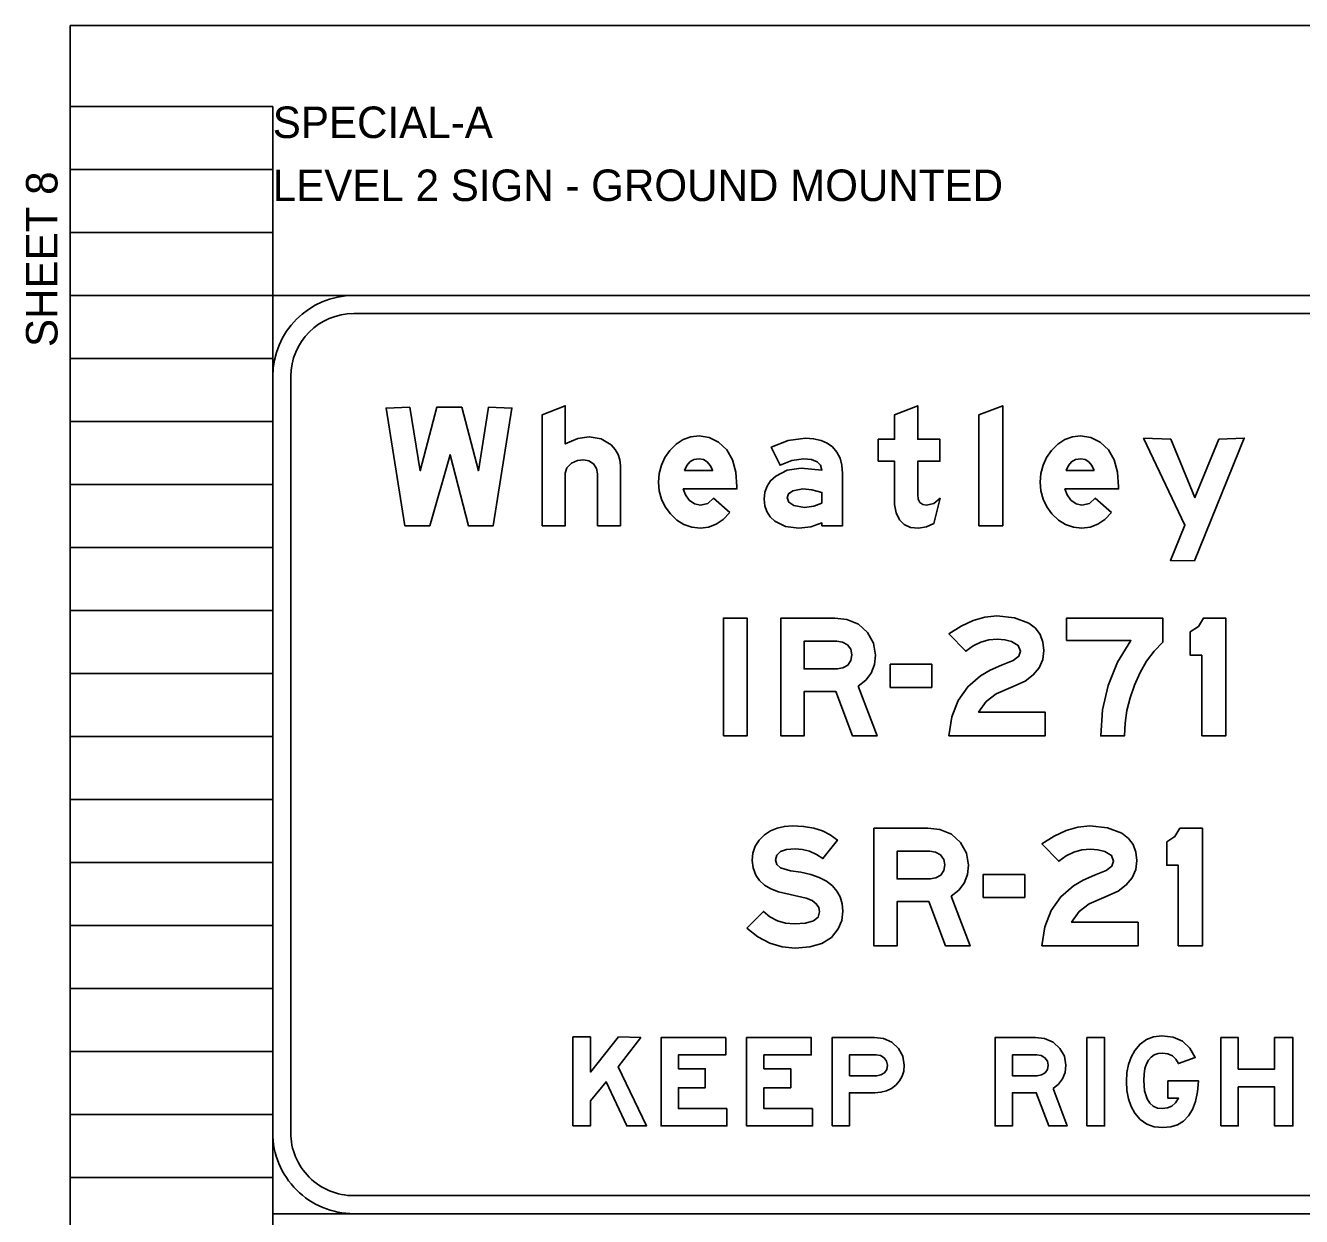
# Model space of a CAD drawing. Extents: x 1820207 to 1820557, y 740216 to 740315.
# Drawn here: x 1820476.25 to 1820481.92, y 740270.45 to 740275.74 of the extents above; entities that cross this region are included whole.
import ezdxf

# ---------------------------------------------------------------- set-up
doc = ezdxf.new("R2010")
doc.units = 0
for name, color, linetype in [('SC_Scratch1', 7, 'Continuous'), ('SC_Scratch2', 7, 'Continuous'), ('SC_Scratch3', 7, 'Continuous'), ('SH_Text', 7, 'Continuous')]:
    doc.layers.add(name, color=color, linetype=linetype)

msp = doc.modelspace()

# ---------------------------------------------------------------- linework, layer by layer
at = {"layer": 'SC_Scratch1'}
for p, q in [((1820476.451, 740255.2219), (1820476.451, 740275.3819)), ((1820476.451, 740275.3819), (1820477.351, 740275.3819)), ((1820477.351, 740255.2219), (1820477.351, 740275.3819)), ((1820476.451, 740275.1019), (1820477.351, 740275.1019)), ((1820476.451, 740274.8219), (1820477.351, 740274.8219)), ((1820476.451, 740274.5419), (1820477.351, 740274.5419)), ((1820476.451, 740274.2619), (1820477.351, 740274.2619)), ((1820476.451, 740273.9819), (1820477.351, 740273.9819)), ((1820476.451, 740273.7019), (1820477.351, 740273.7019)), ((1820476.451, 740273.4219), (1820477.351, 740273.4219)), ((1820476.451, 740273.1419), (1820477.351, 740273.1419)), ((1820476.451, 740272.8619), (1820477.351, 740272.8619)), ((1820476.451, 740272.5819), (1820477.351, 740272.5819)), ((1820476.451, 740272.3019), (1820477.351, 740272.3019)), ((1820476.451, 740272.0219), (1820477.351, 740272.0219)), ((1820476.451, 740271.7419), (1820477.351, 740271.7419)), ((1820476.451, 740271.4619), (1820477.351, 740271.4619)), ((1820476.451, 740271.1819), (1820477.351, 740271.1819)), ((1820476.451, 740270.9019), (1820477.351, 740270.9019)), ((1820476.451, 740270.6219), (1820477.351, 740270.6219))]:
    msp.add_line(p, q, dxfattribs=at)
at = {"layer": 'SC_Scratch2'}
msp.add_lwpolyline([(1820476.451, 740275.7419), (1820506.951, 740275.7419), (1820506.951, 740254.7419), (1820476.451, 740254.7419)], close=True, dxfattribs=at)
at = {"layer": 'SC_Scratch3'}
for points in [[(1820477.351, 740270.4619), (1820483.591, 740270.4619), (1820483.591, 740274.5419), (1820477.351, 740274.5419), (1820477.351, 740270.4619), (1820477.351, 740270.4619), (1820477.351, 740270.4619)], [(1820477.711, 740274.5419), (1820483.231, 740274.5419)], [(1820483.231, 740274.4619), (1820477.711, 740274.4619)], [(1820477.351, 740270.8219), (1820477.351, 740274.1819)], [(1820477.431, 740274.1819), (1820477.431, 740270.8219)], [(1820477.431, 740274.1819), (1820477.431, 740274.1819), (1820477.431, 740274.1819)], [(1820477.711, 740270.5419), (1820483.231, 740270.5419)], [(1820477.711, 740270.5419), (1820477.711, 740270.5419), (1820477.711, 740270.5419)], [(1820483.231, 740270.4619), (1820477.711, 740270.4619)]]:
    msp.add_lwpolyline(points, dxfattribs=at)
for points in [[(1820477.9378, 740273.5186), (1820478.0485, 740273.5186), (1820478.1392, 740273.8346), (1820478.2205, 740273.5186), (1820478.3312, 740273.5186), (1820478.4141, 740274.0416), (1820478.3091, 740274.0459), (1820478.2649, 740273.7632), (1820478.191, 740274.0459), (1820478.0801, 740274.0459), (1820478.0064, 740273.7632), (1820477.9599, 740274.0459), (1820477.855, 740274.0416)], [(1820478.5483, 740273.5186), (1820478.6508, 740273.5186), (1820478.6508, 740273.7532), (1820478.6578, 740273.7766), (1820478.6792, 740273.7964), (1820478.7048, 740273.8083), (1820478.7316, 740273.8123), (1820478.7561, 740273.8076), (1820478.7763, 740273.7938), (1820478.7897, 740273.7735), (1820478.7944, 740273.7495), (1820478.7944, 740273.5186), (1820478.8963, 740273.5186), (1820478.8963, 740273.7849), (1820478.8936, 740273.8112), (1820478.8859, 740273.8355), (1820478.8728, 740273.8576), (1820478.8547, 740273.8778), (1820478.8101, 740273.9051), (1820478.7578, 740273.9142), (1820478.7061, 740273.9062), (1820478.6508, 740273.8825), (1820478.6508, 740274.0519), (1820478.5483, 740274.0115)], [(1820480.0416, 740273.8058), (1820480.1144, 740273.8058), (1820480.1139, 740273.6139), (1820480.1208, 740273.5763), (1820480.1358, 740273.5457), (1820480.1575, 740273.5242), (1820480.1856, 740273.5118), (1820480.2205, 740273.5084), (1820480.2568, 740273.5143), (1820480.2896, 740273.5293), (1820480.3169, 740273.641), (1820480.2892, 740273.6184), (1820480.2568, 740273.6108), (1820480.2394, 740273.6138), (1820480.2271, 740273.6226), (1820480.2196, 740273.6371), (1820480.2172, 740273.6576), (1820480.2172, 740273.8058), (1820480.316, 740273.8058), (1820480.316, 740273.9037), (1820480.2172, 740273.9037), (1820480.2172, 740274.0519), (1820480.1144, 740274.012), (1820480.1144, 740273.9037), (1820480.0416, 740273.9037)], [(1820480.4896, 740273.5186), (1820480.595, 740273.5186), (1820480.595, 740274.0519), (1820480.4896, 740274.0115)], [(1820479.3821, 740273.5778), (1820479.3098, 740273.6415), (1820479.2841, 740273.6184), (1820479.2513, 740273.6108), (1820479.2249, 740273.6163), (1820479.2018, 740273.6332), (1820479.1848, 740273.6558), (1820479.1754, 740273.6826), (1820479.4137, 740273.6826), (1820479.4137, 740273.6915), (1820479.4091, 740273.7575), (1820479.3942, 740273.8126), (1820479.3685, 740273.8569), (1820479.3324, 740273.8905), (1820479.2901, 740273.9115), (1820479.2454, 740273.9186), (1820479.2085, 740273.9144), (1820479.1748, 740273.9022), (1820479.144, 740273.8819), (1820479.1162, 740273.8537), (1820479.094, 740273.8216), (1820479.0783, 740273.7876), (1820479.0686, 740273.7514), (1820479.0656, 740273.7131), (1820479.0688, 740273.6737), (1820479.0786, 740273.6371), (1820479.0949, 740273.603), (1820479.1179, 740273.5716), (1820479.1464, 740273.5437), (1820479.1783, 740273.524), (1820479.2132, 740273.5122), (1820479.2513, 740273.5084), (1820479.288, 740273.5127), (1820479.3221, 740273.5256), (1820479.3534, 740273.5472)], [(1820479.7913, 740273.5186), (1820479.8835, 740273.5186), (1820479.8835, 740273.7514), (1820479.8806, 740273.7875), (1820479.8725, 740273.8192), (1820479.8585, 740273.8463), (1820479.8393, 740273.869), (1820479.8156, 740273.886), (1820479.7875, 740273.8983), (1820479.7548, 740273.9058), (1820479.718, 740273.9083), (1820479.6412, 740273.8983), (1820479.5665, 740273.8687), (1820479.6059, 740273.7881), (1820479.6583, 740273.8089), (1820479.7104, 740273.816), (1820479.7447, 740273.8128), (1820479.7697, 740273.8035), (1820479.7851, 740273.7878), (1820479.7913, 740273.766), (1820479.6993, 740273.775), (1820479.6373, 740273.7662), (1820479.5861, 740273.7397), (1820479.5636, 740273.7188), (1820479.5476, 740273.6948), (1820479.538, 740273.6676), (1820479.535, 740273.6371), (1820479.5378, 740273.6076), (1820479.5466, 740273.5817), (1820479.5612, 740273.5591), (1820479.5817, 740273.5399), (1820479.6298, 740273.5162), (1820479.6893, 740273.5084), (1820479.7421, 740273.5142), (1820479.7913, 740273.5317)], [(1820481.0781, 740273.5778), (1820481.0058, 740273.6415), (1820480.9801, 740273.6184), (1820480.9473, 740273.6108), (1820480.9209, 740273.6163), (1820480.8978, 740273.6332), (1820480.8808, 740273.6558), (1820480.8714, 740273.6826), (1820481.1097, 740273.6826), (1820481.1097, 740273.6915), (1820481.1051, 740273.7575), (1820481.0902, 740273.8126), (1820481.0645, 740273.8569), (1820481.0284, 740273.8905), (1820480.9861, 740273.9115), (1820480.9414, 740273.9186), (1820480.9045, 740273.9144), (1820480.8708, 740273.9022), (1820480.84, 740273.8819), (1820480.8122, 740273.8537), (1820480.79, 740273.8216), (1820480.7743, 740273.7876), (1820480.7646, 740273.7514), (1820480.7616, 740273.7131), (1820480.7648, 740273.6737), (1820480.7746, 740273.6371), (1820480.7909, 740273.603), (1820480.8139, 740273.5716), (1820480.8424, 740273.5437), (1820480.8743, 740273.524), (1820480.9092, 740273.5122), (1820480.9473, 740273.5084), (1820480.984, 740273.5127), (1820481.0181, 740273.5256), (1820481.0494, 740273.5472)], [(1820481.2203, 740273.9083), (1820481.4044, 740273.5211), (1820481.3405, 740273.3647), (1820481.447, 740273.363), (1820481.6686, 740273.9083), (1820481.5558, 740273.9037), (1820481.4492, 740273.644), (1820481.342, 740273.9037)], [(1820479.3061, 740273.7647), (1820479.1811, 740273.7647), (1820479.1908, 740273.7871), (1820479.2047, 740273.8032), (1820479.223, 740273.8128), (1820479.2456, 740273.816), (1820479.265, 740273.8128), (1820479.2815, 740273.8032), (1820479.2951, 740273.7871)], [(1820481.0021, 740273.7647), (1820480.8771, 740273.7647), (1820480.8868, 740273.7871), (1820480.9007, 740273.8032), (1820480.919, 740273.8128), (1820480.9416, 740273.816), (1820480.961, 740273.8128), (1820480.9775, 740273.8032), (1820480.9911, 740273.7871)], [(1820479.7913, 740273.62), (1820479.7556, 740273.6054), (1820479.7139, 740273.6006), (1820479.666, 740273.6096), (1820479.6445, 740273.6237), (1820479.6375, 740273.6424), (1820479.6437, 740273.6614), (1820479.6625, 740273.6746), (1820479.7067, 740273.6826), (1820479.7469, 740273.6788), (1820479.7913, 740273.6673)], [(1820480.3563, 740272.5852), (1820480.7835, 740272.5852), (1820480.7835, 740272.6906), (1820480.4877, 740272.6906), (1820480.5218, 740272.7384), (1820480.5657, 740272.7727), (1820480.6306, 740272.7999), (1820480.6944, 740272.8283), (1820480.731, 740272.8562), (1820480.7572, 740272.8882), (1820480.7729, 740272.9242), (1820480.7782, 740272.9641), (1820480.7739, 740273.0022), (1820480.7612, 740273.0352), (1820480.7401, 740273.0631), (1820480.7107, 740273.086), (1820480.6476, 740273.1104), (1820480.5683, 740273.1186), (1820480.516, 740273.1134), (1820480.4633, 740273.0983), (1820480.4099, 740273.0732), (1820480.3563, 740273.0381), (1820480.4306, 740272.9613), (1820480.463, 740272.9849), (1820480.4973, 740273.0017), (1820480.5332, 740273.0118), (1820480.571, 740273.0152), (1820480.6048, 740273.0126), (1820480.6348, 740273.0051), (1820480.6644, 740272.987), (1820480.6744, 740272.9613), (1820480.6662, 740272.9391), (1820480.6421, 740272.9197), (1820480.5894, 740272.8992), (1820480.5397, 740272.8778), (1820480.4966, 740272.8527), (1820480.4397, 740272.8035), (1820480.3976, 740272.7427), (1820480.3696, 740272.6698)], [(1820479.3536, 740272.5852), (1820479.459, 740272.5852), (1820479.459, 740273.1083), (1820479.3536, 740273.1083)], [(1820479.9531, 740272.8059), (1820479.9864, 740272.8325), (1820480.0102, 740272.8645), (1820480.0247, 740272.9019), (1820480.0295, 740272.9445), (1820480.0205, 740272.9975), (1820479.9939, 740273.0447), (1820479.9534, 740273.0813), (1820479.9029, 740273.103), (1820479.849, 740273.1083), (1820479.6096, 740273.1083), (1820479.6096, 740272.5852), (1820479.7122, 740272.5852), (1820479.7122, 740272.782), (1820479.8538, 740272.782), (1820479.9275, 740272.5852), (1820480.0369, 740272.5852)], [(1820480.879, 740273.0087), (1820481.1648, 740273.0087), (1820481.1058, 740272.9123), (1820481.0639, 740272.8097), (1820481.0387, 740272.7006), (1820481.0304, 740272.5852), (1820481.1358, 740272.5852), (1820481.1385, 740272.6419), (1820481.1469, 740272.6985), (1820481.1607, 740272.7548), (1820481.1802, 740272.8107), (1820481.2052, 740272.8663), (1820481.2346, 740272.9166), (1820481.2682, 740272.9617), (1820481.3062, 740273.0016), (1820481.3062, 740273.1083), (1820480.879, 740273.1083)], [(1820481.4794, 740272.5852), (1820481.5864, 740272.5852), (1820481.5864, 740273.1083), (1820481.4867, 740273.1083), (1820481.4646, 740273.0712), (1820481.4283, 740273.0471), (1820481.4283, 740272.9438), (1820481.4794, 740272.9438)], [(1820479.925, 740272.945), (1820479.9202, 740272.9198), (1820479.9061, 740272.8999), (1820479.8849, 740272.887), (1820479.8596, 740272.8826), (1820479.7122, 740272.8826), (1820479.7122, 740273.0057), (1820479.8574, 740273.0057), (1820479.8833, 740273.0016), (1820479.9053, 740272.9892), (1820479.9201, 740272.9698)], [(1820480.2795, 740272.9031), (1820480.095, 740272.9031), (1820480.095, 740272.8006), (1820480.2795, 740272.8006)], [(1820479.4576, 740271.7307), (1820479.5071, 740271.6916), (1820479.5595, 740271.6639), (1820479.6145, 740271.6472), (1820479.6724, 740271.6417), (1820479.7379, 740271.647), (1820479.7918, 740271.6629), (1820479.8339, 740271.6897), (1820479.8643, 740271.7274), (1820479.8797, 740271.7653), (1820479.8849, 740271.8063), (1820479.8818, 740271.8394), (1820479.8731, 740271.8692), (1820479.8584, 740271.8957), (1820479.838, 740271.919), (1820479.8118, 740271.9389), (1820479.7797, 740271.9556), (1820479.7418, 740271.9688), (1820479.6981, 740271.979), (1820479.6518, 740271.9858), (1820479.6074, 740271.9992), (1820479.5908, 740272.0134), (1820479.5853, 740272.0346), (1820479.5906, 740272.0556), (1820479.607, 740272.0707), (1820479.6342, 740272.0798), (1820479.6724, 740272.0828), (1820479.705, 740272.0801), (1820479.7368, 740272.0721), (1820479.7671, 740272.0586), (1820479.7962, 740272.04), (1820479.8606, 740272.1219), (1820479.8275, 740272.1453), (1820479.7942, 740272.1626), (1820479.755, 740272.1751), (1820479.7102, 740272.1826), (1820479.6597, 740272.1852), (1820479.6248, 740272.1826), (1820479.5925, 740272.1751), (1820479.563, 740272.1625), (1820479.5362, 740272.1448), (1820479.5121, 740272.1212), (1820479.4949, 740272.0945), (1820479.4847, 740272.0644), (1820479.4813, 740272.0311), (1820479.4853, 740271.9985), (1820479.4977, 740271.9666), (1820479.5139, 740271.9424), (1820479.5362, 740271.9219), (1820479.5645, 740271.9051), (1820479.599, 740271.8921), (1820479.7219, 740271.8638), (1820479.7478, 740271.8531), (1820479.7666, 740271.8395), (1820479.7776, 740271.8229), (1820479.7815, 740271.803), (1820479.7744, 740271.7794), (1820479.7535, 740271.7628), (1820479.7185, 740271.7527), (1820479.6696, 740271.7495), (1820479.6297, 740271.7528), (1820479.5935, 740271.7634), (1820479.5606, 740271.7807), (1820479.5315, 740271.8054)], [(1820480.3664, 740271.8725), (1820480.3997, 740271.8992), (1820480.4235, 740271.9312), (1820480.438, 740271.9686), (1820480.4428, 740272.0111), (1820480.4338, 740272.0642), (1820480.4072, 740272.1113), (1820480.3667, 740272.148), (1820480.3162, 740272.1697), (1820480.2623, 740272.175), (1820480.023, 740272.175), (1820480.023, 740271.6519), (1820480.1255, 740271.6519), (1820480.1255, 740271.8487), (1820480.2672, 740271.8487), (1820480.3409, 740271.6519), (1820480.4502, 740271.6519)], [(1820480.7696, 740271.6519), (1820481.1969, 740271.6519), (1820481.1969, 740271.7573), (1820480.901, 740271.7573), (1820480.9351, 740271.8051), (1820480.9791, 740271.8394), (1820481.044, 740271.8666), (1820481.1077, 740271.895), (1820481.1443, 740271.9229), (1820481.1705, 740271.9549), (1820481.1863, 740271.9908), (1820481.1916, 740272.0307), (1820481.1872, 740272.0688), (1820481.1746, 740272.1019), (1820481.1534, 740272.1298), (1820481.1241, 740272.1527), (1820481.061, 740272.177), (1820480.9816, 740272.1852), (1820480.9294, 740272.1801), (1820480.8767, 740272.165), (1820480.8233, 740272.1399), (1820480.7696, 740272.1048), (1820480.844, 740272.028), (1820480.8763, 740272.0516), (1820480.9107, 740272.0684), (1820480.9465, 740272.0785), (1820480.9844, 740272.0819), (1820481.0181, 740272.0792), (1820481.0482, 740272.0718), (1820481.0778, 740272.0537), (1820481.0877, 740272.028), (1820481.0795, 740272.0057), (1820481.0555, 740271.9863), (1820481.0028, 740271.9658), (1820480.9531, 740271.9445), (1820480.91, 740271.9194), (1820480.8531, 740271.8701), (1820480.811, 740271.8094), (1820480.7829, 740271.7365)], [(1820481.3754, 740271.6519), (1820481.4824, 740271.6519), (1820481.4824, 740272.175), (1820481.3827, 740272.175), (1820481.3606, 740272.1379), (1820481.3243, 740272.1138), (1820481.3243, 740272.0105), (1820481.3754, 740272.0105)], [(1820480.3383, 740272.0117), (1820480.3335, 740271.9865), (1820480.3194, 740271.9666), (1820480.2982, 740271.9537), (1820480.273, 740271.9493), (1820480.1255, 740271.9493), (1820480.1255, 740272.0724), (1820480.2707, 740272.0724), (1820480.2967, 740272.0682), (1820480.3186, 740272.0559), (1820480.3334, 740272.0365)], [(1820480.6928, 740271.9698), (1820480.5083, 740271.9698), (1820480.5083, 740271.8673), (1820480.6928, 740271.8673)], [(1820478.685, 740270.8519), (1820478.7624, 740270.8519), (1820478.7624, 740270.9639), (1820478.8324, 740271.0485), (1820478.9239, 740270.8519), (1820479.0113, 740270.8519), (1820478.8863, 740271.1151), (1820478.9864, 740271.2442), (1820478.8878, 740271.2474), (1820478.7624, 740271.0912), (1820478.7624, 740271.2474), (1820478.685, 740271.2474)], [(1820479.3697, 740270.9288), (1820479.1541, 740270.9288), (1820479.1541, 740271.0211), (1820479.2732, 740271.0211), (1820479.2732, 740271.1057), (1820479.1541, 740271.1057), (1820479.1541, 740271.1673), (1820479.3642, 740271.1673), (1820479.3642, 740271.2442), (1820479.077, 740271.2442), (1820479.077, 740270.8519), (1820479.3697, 740270.8519)], [(1820479.7497, 740270.9288), (1820479.5341, 740270.9288), (1820479.5341, 740271.0211), (1820479.6532, 740271.0211), (1820479.6532, 740271.1057), (1820479.5341, 740271.1057), (1820479.5341, 740271.1673), (1820479.7442, 740271.1673), (1820479.7442, 740271.2442), (1820479.457, 740271.2442), (1820479.457, 740270.8519), (1820479.7497, 740270.8519)], [(1820479.837, 740270.8519), (1820479.9139, 740270.8519), (1820479.9139, 740270.9995), (1820480.0273, 740270.9995), (1820480.054, 740271.0015), (1820480.0784, 740271.0079), (1820480.1005, 740271.0185), (1820480.1202, 740271.0334), (1820480.1363, 740271.0515), (1820480.148, 740271.0724), (1820480.155, 740271.0959), (1820480.1574, 740271.1221), (1820480.1508, 740271.1614), (1820480.1313, 740271.1966), (1820480.1016, 740271.2241), (1820480.0648, 740271.2403), (1820480.0248, 740271.2442), (1820479.837, 740271.2442)], [(1820480.8185, 740271.0174), (1820480.8435, 740271.0374), (1820480.8614, 740271.0614), (1820480.8722, 740271.0894), (1820480.8759, 740271.1213), (1820480.8691, 740271.1611), (1820480.8491, 740271.1965), (1820480.8188, 740271.224), (1820480.7809, 740271.2402), (1820480.7405, 740271.2442), (1820480.561, 740271.2442), (1820480.561, 740270.8519), (1820480.6379, 740270.8519), (1820480.6379, 740270.9995), (1820480.7441, 740270.9995), (1820480.7994, 740270.8519), (1820480.8814, 740270.8519)], [(1820480.969, 740270.8519), (1820481.048, 740270.8519), (1820481.048, 740271.2442), (1820480.969, 740271.2442)], [(1820481.3295, 740271.0519), (1820481.3295, 740270.975), (1820481.3766, 740270.975), (1820481.3635, 740270.9548), (1820481.3469, 740270.9403), (1820481.3269, 740270.9317), (1820481.3037, 740270.9288), (1820481.2822, 740270.9314), (1820481.2641, 740270.9395), (1820481.249, 740270.953), (1820481.2371, 740270.9718), (1820481.2256, 740271.0078), (1820481.2219, 740271.0535), (1820481.2231, 740271.0818), (1820481.227, 740271.1064), (1820481.2334, 740271.1273), (1820481.2427, 740271.1445), (1820481.2543, 740271.1578), (1820481.2687, 740271.1673), (1820481.2857, 740271.173), (1820481.3053, 740271.175), (1820481.3295, 740271.1721), (1820481.3495, 740271.1634), (1820481.3649, 740271.149), (1820481.3758, 740271.1288), (1820481.4503, 740271.1561), (1820481.4264, 740271.1979), (1820481.3938, 740271.2278), (1820481.3525, 740271.2459), (1820481.3024, 740271.2519), (1820481.2656, 740271.2478), (1820481.2333, 740271.2356), (1820481.2053, 740271.2153), (1820481.1817, 740271.1871), (1820481.1655, 740271.1575), (1820481.1541, 740271.1249), (1820481.1472, 740271.0888), (1820481.145, 740271.0496), (1820481.1472, 740271.0087), (1820481.1543, 740270.9716), (1820481.166, 740270.9382), (1820481.1826, 740270.9086), (1820481.2066, 740270.8804), (1820481.2354, 740270.8603), (1820481.2688, 740270.8482), (1820481.3071, 740270.8442), (1820481.3418, 740270.8475), (1820481.3724, 740270.8572), (1820481.3985, 740270.8734), (1820481.4206, 740270.8961), (1820481.4382, 740270.9253), (1820481.4516, 740270.961), (1820481.4608, 740271.0032), (1820481.4657, 740271.0519)], [(1820481.565, 740270.8519), (1820481.6419, 740270.8519), (1820481.6419, 740271.0255), (1820481.8034, 740271.0255), (1820481.8034, 740270.8519), (1820481.8845, 740270.8519), (1820481.8845, 740271.2442), (1820481.8034, 740271.2442), (1820481.8034, 740271.1043), (1820481.6419, 740271.1043), (1820481.6419, 740271.2442), (1820481.565, 740271.2442)], [(1820479.9139, 740271.075), (1820479.9139, 740271.1673), (1820480.0325, 740271.1673), (1820480.0517, 740271.1642), (1820480.0681, 740271.1549), (1820480.0792, 740271.1403), (1820480.0831, 740271.1217), (1820480.0796, 740271.1028), (1820480.0693, 740271.0879), (1820480.0538, 740271.0782), (1820480.0349, 740271.075)], [(1820480.7975, 740271.1217), (1820480.7939, 740271.1028), (1820480.7833, 740271.0879), (1820480.7674, 740271.0782), (1820480.7485, 740271.075), (1820480.6379, 740271.075), (1820480.6379, 740271.1673), (1820480.7467, 740271.1673), (1820480.7662, 740271.1642), (1820480.7827, 740271.1549), (1820480.7938, 740271.1403)]]:
    msp.add_lwpolyline(points, close=True, dxfattribs=at)
for centre, radius, start, end in [((1820477.711, 740274.1819), 0.36, 90.0002, 179.9999), ((1820477.711, 740274.1819), 0.28, 90.0002, 179.9998), ((1820477.711, 740270.8219), 0.36, 179.9998, 270.0001), ((1820477.711, 740270.8219), 0.28, 179.9999, 270.0001)]:
    msp.add_arc(centre, radius, start, end, dxfattribs=at)

# ---------------------------------------------------------------- texts
at = {"layer": 'SH_Text'}
for s, p in [('SPECIAL-A', (1820477.351, 740275.2419)), ('LEVEL 2 SIGN - GROUND MOUNTED', (1820477.351, 740274.9619))]:
    msp.add_text(s, height=0.14, dxfattribs=at).set_placement(p)
msp.add_text('SHEET 8', height=0.14, rotation=90, dxfattribs=at).set_placement((1820476.3944, 740274.3132))

doc.saveas('drawing.dxf')
